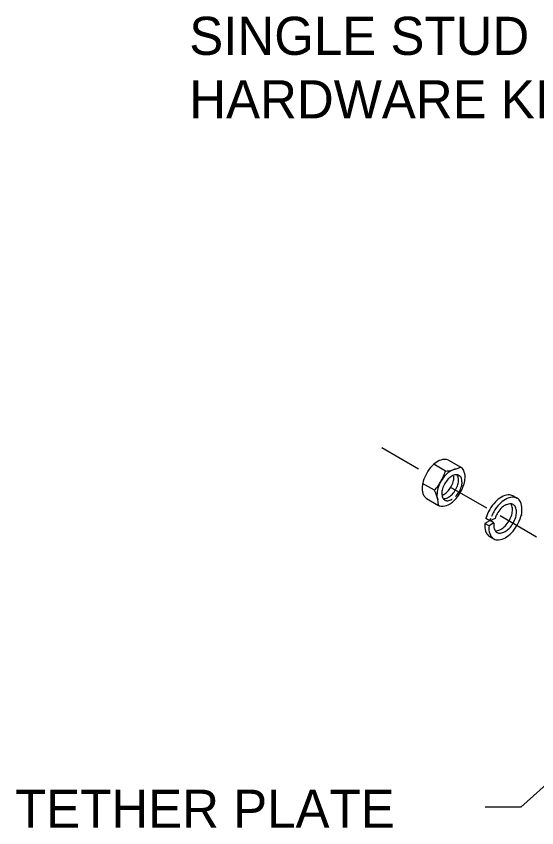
# Model space of a CAD drawing. Extents: x -1316.3 to -1303.1, y 2853.3 to 2863.3.
# Drawn here: x -1312.424 to -1311.604, y 2862.011 to 2863.289 of the extents above; entities that cross this region are included whole.
import ezdxf

# ---------------------------------------------------------------- set-up
doc = ezdxf.new("R2010")
doc.units = 0
for name, color, linetype in [('DETL-DIMS', 7, 'Continuous'), ('DETL-LINE', 7, 'Continuous'), ('DETL-NOTE', 7, 'Continuous')]:
    doc.layers.add(name, color=color, linetype=linetype)

msp = doc.modelspace()

# ---------------------------------------------------------------- linework, layer by layer
at = {"layer": 'DETL-DIMS'}
for p, q in [((-1311.848, 2862.61), (-1311.7904, 2862.5767)), ((-1311.7411, 2862.5483), (-1311.6835, 2862.515)), ((-1311.6622, 2862.5028), (-1311.6047, 2862.4695)), ((-1311.4545, 2862.2005), (-1311.6296, 2862.0437)), ((-1311.6296, 2862.0437), (-1311.6857, 2862.0437))]:
    msp.add_line(p, q, dxfattribs=at)
at = {"layer": 'DETL-LINE'}
for p, q in [((-1311.748, 2862.573), (-1311.7665, 2862.5837)), ((-1311.7435, 2862.5903), (-1311.724, 2862.5791)), ((-1311.7654, 2862.5427), (-1311.784, 2862.5535)), ((-1311.6417, 2862.5338), (-1311.6353, 2862.5302)), ((-1311.7777, 2862.5298), (-1311.7591, 2862.519)), ((-1311.6787, 2862.4948), (-1311.686, 2862.4904)), ((-1311.6785, 2862.4947), (-1311.6846, 2862.4982)), ((-1311.6785, 2862.4947), (-1311.6769, 2862.4988)), ((-1311.6699, 2862.4982), (-1311.6785, 2862.4947)), ((-1311.6718, 2862.4913), (-1311.678, 2862.4949)), ((-1311.6795, 2862.4866), (-1311.686, 2862.4904)), ((-1311.6718, 2862.4913), (-1311.6795, 2862.4866)), ((-1311.6785, 2862.47), (-1311.6722, 2862.4663))]:
    msp.add_line(p, q, dxfattribs=at)
for centre, radius, start, end in [((-1311.7404, 2862.5539), 0.0396, 120, 136.5505), ((-1311.7476, 2862.5663), 0.0253, 95.6571, 120), ((-1311.7489, 2862.5795), 0.012, 61.3029, 95.6571), ((-1311.7258, 2862.54), 0.0598, 150, 163.4495), ((-1311.7258, 2862.54), 0.0598, 136.5505, 150), ((-1311.8304, 2862.6004), 0.0869, 330, 341.5646), ((-1311.7486, 2862.6126), 0.0396, 271.0705, 277.8438), ((-1311.722, 2862.5428), 0.0353, 120, 136.5505), ((-1311.7514, 2862.6327), 0.0598, 277.8438, 291.2933), ((-1311.7284, 2862.5538), 0.0226, 98.3818, 120), ((-1311.7507, 2862.6329), 0.0598, 290.5728, 296.0163), ((-1311.7303, 2862.5688), 0.012, 60, 60.5953), ((-1311.7303, 2862.5688), 0.012, 24.3429, 60), ((-1311.7425, 2862.5633), 0.0253, 0, 24.3429), ((-1311.7452, 2862.5457), 0.0396, 163.4495, 180), ((-1311.8304, 2862.6004), 0.0869, 318.3837, 330), ((-1311.7089, 2862.5304), 0.0534, 150, 163.4495), ((-1311.7089, 2862.5304), 0.0534, 136.5505, 150), ((-1311.7156, 2862.5339), 0.0388, 136.5505, 150), ((-1311.7251, 2862.5429), 0.0257, 120, 136.5505), ((-1311.7298, 2862.551), 0.0164, 95.6571, 120), ((-1311.7606, 2862.5635), 0.0257, 343.4495, 360), ((-1311.7513, 2862.5635), 0.0164, 0, 6.0217), ((-1311.7306, 2862.5595), 0.00777, 60, 95.6571), ((-1311.736, 2862.5628), 0.00777, 24.3429, 29.6029), ((-1311.7439, 2862.5592), 0.0164, 360, 24.3429), ((-1311.7532, 2862.5592), 0.0257, 343.4495, 0), ((-1311.7306, 2862.5595), 0.00777, 24.3429, 60), ((-1311.7385, 2862.556), 0.0164, 360, 24.3429), ((-1311.7592, 2862.5649), 0.0421, 343.4495, 356.0157), ((-1311.7568, 2862.5633), 0.0396, 358.0851, 0), ((-1311.7595, 2862.5457), 0.0253, 180, 204.3429), ((-1311.7262, 2862.5355), 0.0353, 163.4495, 180), ((-1311.7282, 2862.5376), 0.0257, 163.4495, 180), ((-1311.7156, 2862.5339), 0.0388, 150, 163.4495), ((-1311.7732, 2862.5673), 0.0388, 316.5505, 330), ((-1311.7732, 2862.5673), 0.0388, 330, 343.4495), ((-1311.7657, 2862.563), 0.0388, 330, 343.4495), ((-1311.7603, 2862.5597), 0.0388, 330, 343.4495), ((-1311.7798, 2862.571), 0.0636, 330, 343.4495), ((-1311.7477, 2862.556), 0.0257, 343.4495, 0), ((-1311.7716, 2862.5403), 0.012, 204.3429, 239.5811), ((-1311.8001, 2862.5234), 0.0396, 22.1562, 28.9295), ((-1311.8188, 2862.5158), 0.0598, 8.7067, 22.1562), ((-1311.739, 2862.5355), 0.0226, 180, 199.7392), ((-1311.7375, 2862.5376), 0.0164, 180, 204.3429), ((-1311.759, 2862.5502), 0.0164, 293.9783, 300), ((-1311.7637, 2862.5583), 0.0257, 300, 316.5505), ((-1311.7516, 2862.5459), 0.0164, 275.6571, 300), ((-1311.7562, 2862.554), 0.0257, 300, 316.5505), ((-1311.7657, 2862.563), 0.0388, 316.5505, 330), ((-1311.7798, 2862.571), 0.0636, 316.5505, 330), ((-1311.7603, 2862.5597), 0.0388, 316.5505, 330), ((-1311.7508, 2862.5507), 0.0257, 316.5074, 316.5505), ((-1311.639, 2862.4955), 0.0421, 120, 136.5505), ((-1311.6466, 2862.5087), 0.0269, 95.6571, 120), ((-1311.6403, 2862.505), 0.0269, 95.6571, 120), ((-1311.648, 2862.5228), 0.0128, 60, 95.6571), ((-1311.6417, 2862.5191), 0.0128, 60, 95.6571), ((-1311.648, 2862.5228), 0.0128, 58.0522, 60), ((-1311.8188, 2862.5158), 0.0598, 3.2632, 8.7067), ((-1311.753, 2862.5295), 0.012, 239.4047, 240), ((-1311.753, 2862.5295), 0.012, 240, 275.6571), ((-1311.7453, 2862.5341), 0.00777, 204.3429, 240), ((-1311.7543, 2862.5428), 0.0253, 275.6571, 300), ((-1311.7507, 2862.5373), 0.00777, 270.3971, 275.6571), ((-1311.7453, 2862.5341), 0.00777, 240, 275.6571), ((-1311.7462, 2862.5427), 0.0164, 275.6571, 300), ((-1311.7615, 2862.5552), 0.0396, 300, 303.3228), ((-1311.7642, 2862.5562), 0.0421, 304.5132, 316.5505), ((-1311.7508, 2862.5507), 0.0257, 300, 300.599), ((-1311.6234, 2862.4807), 0.0636, 136.5505, 150), ((-1311.6171, 2862.4771), 0.0636, 136.5505, 150), ((-1311.6327, 2862.4919), 0.0421, 120, 136.5505), ((-1311.6398, 2862.494), 0.029, 120, 136.5505), ((-1311.645, 2862.503), 0.0185, 95.6571, 120), ((-1311.646, 2862.5127), 0.00878, 60, 95.6571), ((-1311.6523, 2862.5164), 0.00878, 24.3429, 35.3574), ((-1311.6612, 2862.5124), 0.0185, 0, 24.3429), ((-1311.646, 2862.5127), 0.00878, 24.3429, 60), ((-1311.6417, 2862.5191), 0.0128, 24.3429, 60), ((-1311.6546, 2862.5133), 0.0269, 0, 24.3429), ((-1311.6234, 2862.4807), 0.0636, 150, 163.4495), ((-1311.6209, 2862.4811), 0.0583, 151.5685, 159.4574), ((-1311.6328, 2862.4878), 0.0386, 152.3273, 164.3382), ((-1311.629, 2862.4838), 0.0438, 136.5505, 150), ((-1311.6717, 2862.5124), 0.029, 343.4495, 360), ((-1311.6548, 2862.5087), 0.0185, 0, 24.3429), ((-1311.6653, 2862.5087), 0.029, 343.4495, 360), ((-1311.6698, 2862.5133), 0.0421, 343.4495, 0), ((-1311.644, 2862.4868), 0.0421, 163.4495, 164.3417), ((-1311.6859, 2862.5166), 0.0438, 316.5505, 330), ((-1311.6859, 2862.5166), 0.0438, 330, 343.4495), ((-1311.6795, 2862.5129), 0.0438, 330, 343.4495), ((-1311.6904, 2862.5194), 0.0636, 330, 343.4495), ((-1311.6021, 2862.474), 0.0396, 131.0308, 131.1847), ((-1311.644, 2862.4868), 0.0421, 175.2053, 180), ((-1311.6593, 2862.4868), 0.0269, 180, 204.3429), ((-1311.6341, 2862.4807), 0.0458, 172.5661, 176.8707), ((-1311.6529, 2862.4832), 0.0269, 180, 204.3429), ((-1311.6396, 2862.4854), 0.0327, 169.7711, 175.533), ((-1311.6537, 2862.488), 0.0185, 180, 204.3429), ((-1311.6626, 2862.484), 0.00878, 204.3429, 240), ((-1311.6699, 2862.4973), 0.0185, 275.6571, 300), ((-1311.6751, 2862.5064), 0.029, 300, 316.5505), ((-1311.6688, 2862.5027), 0.029, 300, 316.5505), ((-1311.6795, 2862.5129), 0.0438, 316.5505, 330), ((-1311.6904, 2862.5194), 0.0636, 316.5505, 330), ((-1311.6721, 2862.481), 0.0128, 204.3429, 240), ((-1311.6721, 2862.481), 0.0128, 240, 241.3736), ((-1311.6658, 2862.4774), 0.0128, 204.3429, 240), ((-1311.6689, 2862.4876), 0.00878, 264.6426, 275.6571), ((-1311.6626, 2862.484), 0.00878, 240, 275.6571), ((-1311.6672, 2862.4914), 0.0269, 275.6571, 300), ((-1311.6635, 2862.4937), 0.0185, 275.6571, 300), ((-1311.6748, 2862.5046), 0.0421, 300, 316.5505), ((-1311.6068, 2862.4659), 0.0396, 168.7445, 168.9692), ((-1311.6658, 2862.4774), 0.0128, 240, 275.6571)]:
    msp.add_arc(centre, radius, start, end, dxfattribs=at)

# ---------------------------------------------------------------- texts
at = {"layer": 'DETL-NOTE'}
for s, p in [('SINGLE STUD', (-1312.1513, 2863.2285)), ('HARDWARE KIT', (-1312.1513, 2863.1285)), ('TETHER PLATE', (-1312.4254, 2862.0112))]:
    msp.add_text(s, height=0.06, dxfattribs=at).set_placement(p)

doc.saveas('drawing.dxf')
